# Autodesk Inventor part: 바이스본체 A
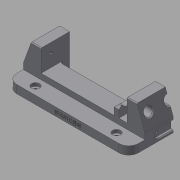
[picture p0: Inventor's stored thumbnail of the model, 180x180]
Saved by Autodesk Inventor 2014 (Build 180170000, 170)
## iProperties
Created: 2017-04
Part Number: 바이스본체 A
Material: 일반
Document SubType Name: Modeling
Designer: mduedu
Density: 1 g/cm^3
Appearance: 기본값
Author: mduedu
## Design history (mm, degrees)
sketch "스케치1"
  geometry: L1 (-75, 0)-(75, 0); L2 (-75, 0)-(-75, 17); L3 (-53, 17)-(53, 17); L4 (75, 17)-(75, 0); L5 (-75, 17)-(-65.173, 44); L6 (-65.173, 44)-(-53, 44); L7 (-53, 44)-(-53, 17); L8 (0, 0)-(0, 17); L9 (75, 17)-(65.173, 44); L10 (65.173, 44)-(53, 44); L11 (53, 44)-(53, 17); 1 further point
  constraints: 22 end point, 4 perpendicular, 2 horizontal alignment, 2 midpoint, 2 symmetric about line, 1 coincident, 1 collinear, 1 horizontal, 1 vertical
  dimensions: "d0" = 150 distance of L1.start L1.end; "d1" = 17 distance of L1.start L2.end; "d2" = 27 distance of L3.start L6.end; "d3" = 22 distance of L3.start L2.end; "d4" = 70 deg angle of L3 L5; "d54" = 20 deg angle of L9 L4
extrude "돌출1" new body sketch "스케치1" stored distance "d5" = 70; taper "d6" = 0 deg
sketch "스케치2"
  geometry: L1 (0, 70)-(106, 70) reference; L2 (106, 70)-(106, 0) reference; L3 (106, 0)-(0, 0) reference; L4 (0, 47)-(106, 47); L5 (106, 47)-(106, 23); L6 (106, 23)-(0, 23); L7 (0, 23)-(0, 47); L8 (0, 70)-(0, 0) reference; 2 further points
  constraints: 8 end point, 2 parallel, 2 point on line, 1 horizontal, 1 horizontal alignment, 1 midpoint, 1 perpendicular
  dimensions: "d7" = 24 distance between parallel lines of L6 L4
extrude "돌출2" cut sketch "스케치2" stored distance "d9" = 70; taper "d10" = 0 deg
sketch "스케치3"
  geometry: L1 (22, -23)-(128, -23) reference; L2 (128, -47)-(22, -47) reference; L3 (22, -18)-(128, -18); L4 (128, -52)-(22, -52); L5 (22, -18)-(22, -52); L6 (128, -18)-(128, -52); 1 further point
  constraints: 8 end point, 3 parallel, 2 point on line, 1 perpendicular
  dimensions: "d11" = 5 distance between parallel lines of L3 L1; "d12" = 5 distance between parallel lines of L4 L2
extrude "돌출3" cut sketch "스케치3" distance "d13" = 12; taper "d14" = 0 deg
fillet "모깎기1" dims "d15" = 3, "d16" = 3
sketch "스케치4"
  geometry: L1 (103, 23)-(3, 23) reference; L2 (0, 26)-(0, 0) reference; L3 (106, 0)-(0, 0) reference; L4 (106, 26)-(106, 0) reference; L5 (96, 0)-(90, 0); L6 (90, 0)-(90, 19.5); L7 (96, 19.5)-(96, 0); L8 (90, 19.5)-(96, 19.5); A1 r 3 centre (3, 26) between (0, 26) and (3, 23) reference; A2 r 3 centre (103, 26) between (103, 23) and (106, 26) reference; 1 further point
  constraints: 8 end point, 2 perpendicular, 1 horizontal, 1 parallel, 1 point on line
  dimensions: "d17" = 10 distance between parallel lines of L7 L4; "d18" = 6 distance between parallel lines of L7 L6; "d27" = 3.5 distance between parallel lines of L8 L1
extrude "돌출4" join sketch "스케치4" distance "d19" = 12; taper "d20" = 0 deg
chamfer "모따기1" distance "d21" = 3; stored, may be unused: second distance "d22" = 2, angle "d23" = 45 deg
chamfer "모따기2" distance "d24" = 3; stored, may be unused: second distance "d25" = 2, angle "d26" = 45 deg
sketch "스케치5"
  geometry: L1 (-15.5, 35.8)-(-15.5, -25.8) reference; L2 (19.5, 0)-(0, 0) reference; C1 r 6.5 at (9.5, 15); 1 further point
  constraints: 1 centre point
  dimensions: "d28" = 13 diameter of C1; "d30" = 15 distance from line of C1.centre L2; "d31" = 25 distance from line of C1.centre L1
extrude "돌출5" cut sketch "스케치5" stored distance "d32" = 12; taper "d33" = 0 deg
sketch "스케치6"
  geometry: C1 r 5 at (-10, 15); C2 r 5 at (-60, 15); A1 r 6.5 centre (-10, 15) between (-15.766, 12) and (-4.234, 12) reference; A2 r 6.5 centre (-60, 15) between (-65.766, 12) and (-54.234, 12) reference; 1 further point
  constraints: 2 centre point, 2 coincident
  dimensions: "d34" = 10 diameter of C1; "d35" = 10 diameter of C2 (= d34)
extrude "돌출6" cut sketch "스케치6" stored distance "d36" = 12; taper "d37" = 0 deg
chamfer "모따기3" distance "d38" = 1; stored, may be unused: second distance "d39" = 2, angle "d40" = 45 deg
chamfer "모따기4" distance "d41" = 1; stored, may be unused: second distance "d42" = 2, angle "d43" = 45 deg
sketch "스케치7"
  geometry: L1 (-35, 35.8)-(-35, -25.8) reference; L2 (-70, 0)-(0, 0) reference; C1 r 5 at (-35, 15); 1 further point
  constraints: 1 centre point, 1 point on line
  dimensions: "d44" = 10 diameter of C1; "d45" = 15 distance from line of C1.centre L2
extrude "돌출7" cut sketch "스케치7" stored distance "d46" = 12; taper "d47" = 0 deg
chamfer "모따기5" distance "d48" = 1; stored, may be unused: second distance "d49" = 2, angle "d50" = 45 deg
node "작업축1"
sketch "스케치8"
  geometry: L1 (-105, 32)-(105, 32) reference; L2 (58, 32)-(64, 32); L3 (64, 32)-(64, 40); L4 (64, 40)-(58, 40); L5 (58, 40)-(58, 32); L6 (53, 38)-(53, 26) reference; 1 further point
  constraints: 8 end point, 2 parallel, 1 horizontal, 1 perpendicular, 1 point on line
  dimensions: "d51" = 5 distance from line of L6 L2.start; "d52" = 6 distance of L3.end L4.end; "d53" = 16 diameter of L4 L1
revolve "회전1" sketch "스케치8" stored, may be unused: angle "d55" = 90 deg
fillet "모깎기2"
chamfer "모따기6" distance "d56" = 1; stored, may be unused: second distance "d57" = 2, angle "d58" = 45 deg
sketch "스케치9"
  geometry: L1 (17.5, 3)-(52.5, 3); L2 (52.5, 13)-(17.5, 13); L3 (70, 0)-(0, 0) reference; L4 (17.5, 8)-(52.5, 8); A1 r 5 centre (17.5, 8) between (17.5, 13) and (17.5, 3); A2 r 5 centre (52.5, 8) between (52.5, 3) and (52.5, 13); 3 further points
  constraints: 6 end point, 4 point on circle, 3 tangent, 2 centre point, 2 midpoint, 2 parallel, 1 horizontal, 1 vertical alignment
  dimensions: "d59" = 35 distance of L4.start L4.end; "d61" = 5 radius of A2; "d62" = 8 distance between parallel lines of L3 L4
extrude "돌출8" cut sketch "스케치9" distance "d63" = 3; taper "d64" = 0 deg
chamfer "모따기7" distance "d65" = 1; stored, may be unused: second distance "d66" = 2, angle "d67" = 45 deg
chamfer "모따기8" distance "d68" = 1; stored, may be unused: second distance "d69" = 2, angle "d70" = 45 deg
feature "분할1"
sketch "스케치10"
  geometry: L1 (35, 27)-(0, 27) reference; L2 (0, 0)-(0, 27) reference; 1 further point
  dimensions: "d85" = 11.5 distance from line of point (12, 15.5) L1; "d86" = 12 distance from line of point (12, 15.5) L2
hole "구멍1" sketch "스케치10" at (12, 15.5) diameter "d71" = 3.242; stored, may be unused: countersink angle "d75" = 90 deg, drill point angle "d77" = 120 deg; dims "d72" = 6, "d73" = 4, "d74" = 2, "d76" = 8
sketch "스케치11"
  geometry: A1 r 5 centre (17.5, 8) between (17.5, 13) and (17.5, 3) reference; 1 further point
  constraints: 1 coincident
hole "구멍3" sketch "스케치11" at (17.5, 8) diameter "d78" = 2.459; stored, may be unused: countersink angle "d82" = 90 deg, drill point angle "d84" = 120 deg; dims "d79" = 4.5, "d80" = 4, "d81" = 2, "d83" = 6
sketch "스케치13"
  geometry: L1 (75, 0)-(75, 35) reference; L2 (-75, 0)-(-75, 35) reference; L3 (-75, 35)-(75, 35); L4 (75, 35)-(75, 55); L5 (75, 55)-(-75, 55); L6 (-75, 55)-(-75, 35); 1 further point
  constraints: 8 end point, 2 parallel, 1 horizontal, 1 perpendicular, 1 point on line
  dimensions: "d90" = 20 distance between parallel lines of L5 L3; "d94" = 150 distance of L4.end L5.end (derived)
extrude "돌출9" join sketch "스케치13" distance "d92" = 10; taper "d93" = 0 deg
sketch "스케치14"
  geometry: L1 (-75, -35)-(-75, -55) reference; L2 (75, -55)-(75, -35) reference; L3 (-75, -45)-(75, -45); 3 further points
  constraints: 2 end point, 2 midpoint, 2 point on line
  dimensions: "d95" = 50 horizontal distance of point (-50, -45) point (0, 0); "d96" = 100 distance of point (50, -45) point (-50, -45)
fillet "모깎기3" dims "d97" = 12
chamfer "모따기9" distance "d98" = 1; stored, may be unused: second distance "d99" = 2, angle "d100" = 45 deg
hole "구멍4" sketch "스케치14" diameter "d101" = 4.134; stored, may be unused: countersink angle "d105" = 90 deg, drill point angle "d107" = 118 deg; dims "d102" = 6, "d103" = 10, "d104" = 4, "d106" = 8
sketch "스케치15"
  geometry: L1 (0, 0)-(126, 0) reference; 3 further points
  constraints: 1 midpoint, 1 vertical alignment, 1 other
  dimensions: "d109" = 5 distance from line of point (63, 5) L1
feature "엠보싱2" sketch "스케치15" dims "d0" = 150, "d1" = 17, "d2" = 27, "d3" = 22, "d4" = 70 deg, "d54" = 20 deg, "d110" = 0.5, "d111" = 0
node "솔리드1"
mirror "대칭1"
mirror "대칭2"
mirror "대칭3"
mirror "대칭4"
node "투영된 루프1"
